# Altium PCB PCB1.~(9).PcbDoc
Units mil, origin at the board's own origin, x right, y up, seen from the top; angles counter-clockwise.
Board outline 1575 x 2005 mil, 2 copper layers (Top Layer, Bottom Layer); 15 components, 10 nets, 36 pads, 0 vias.
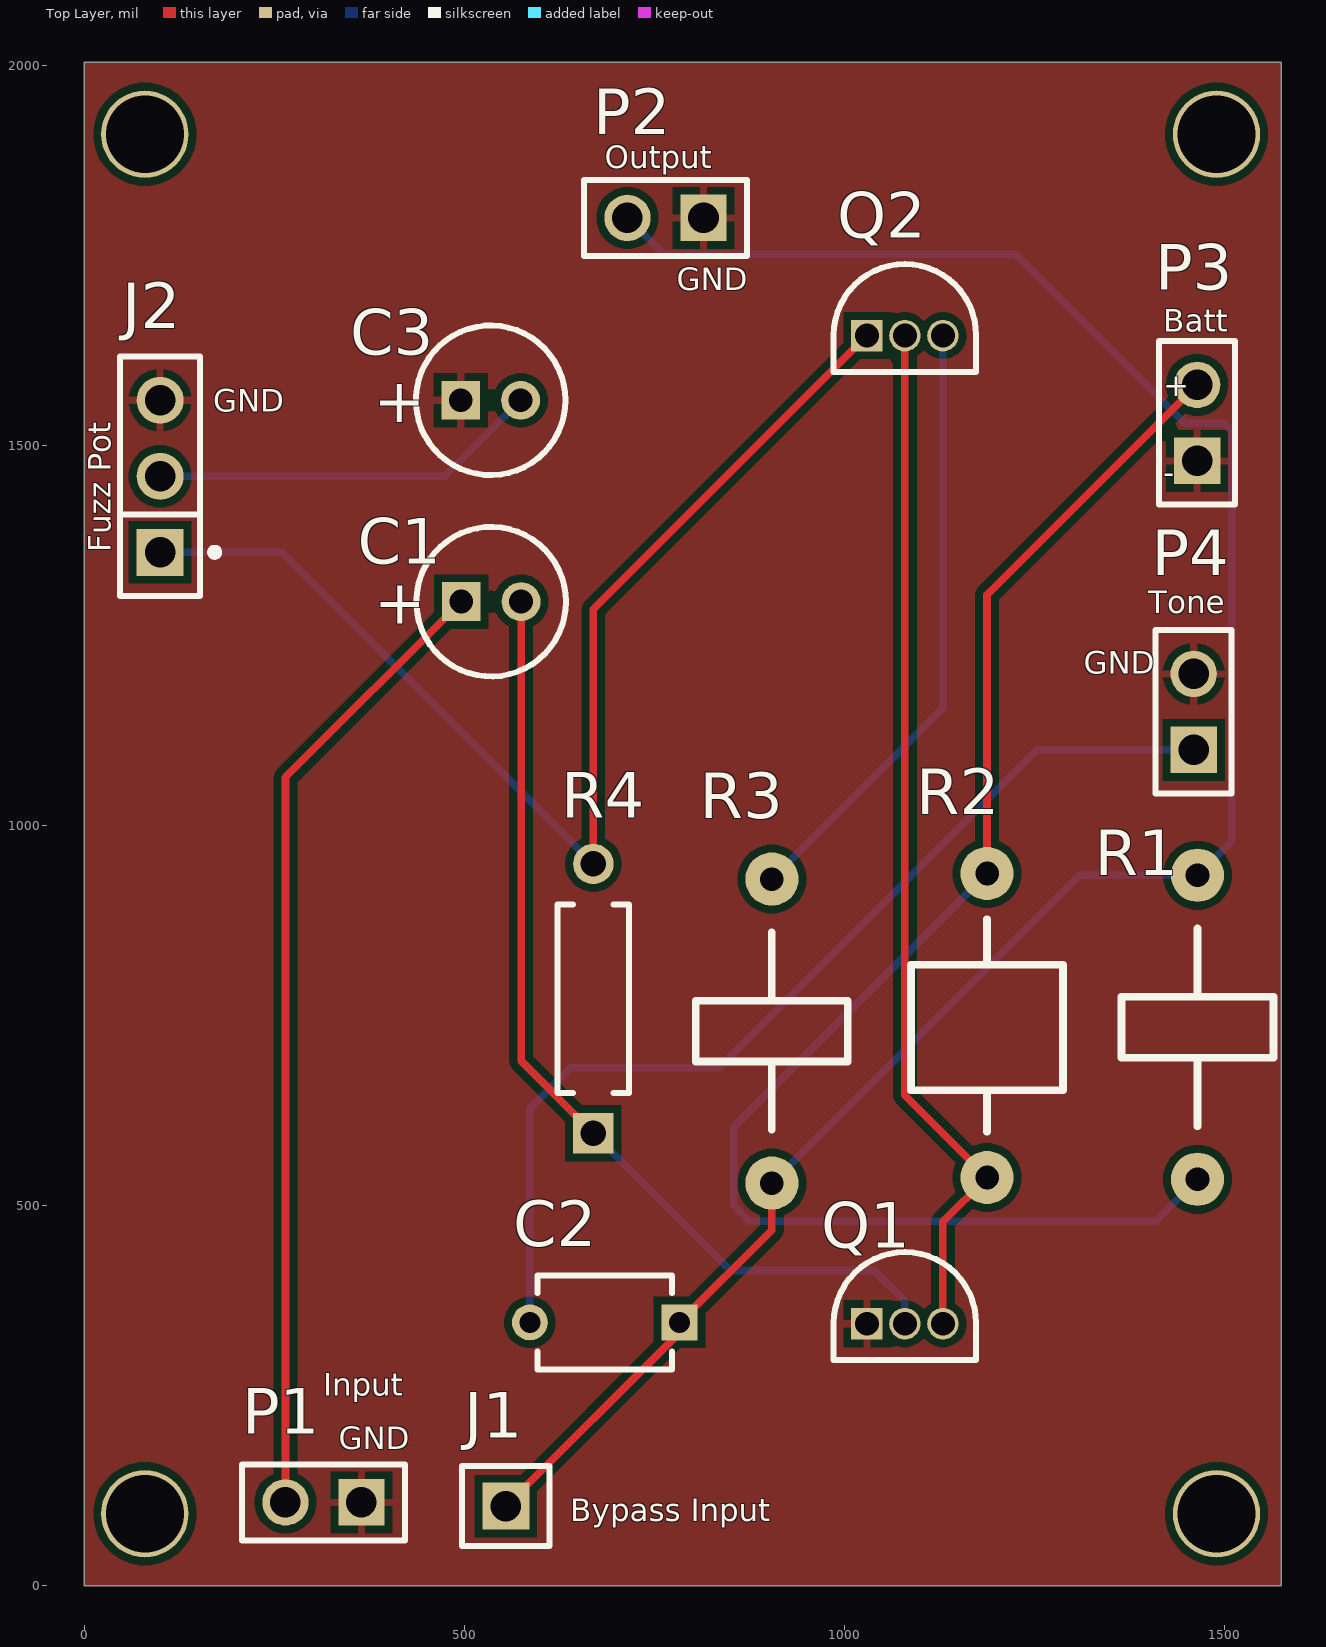
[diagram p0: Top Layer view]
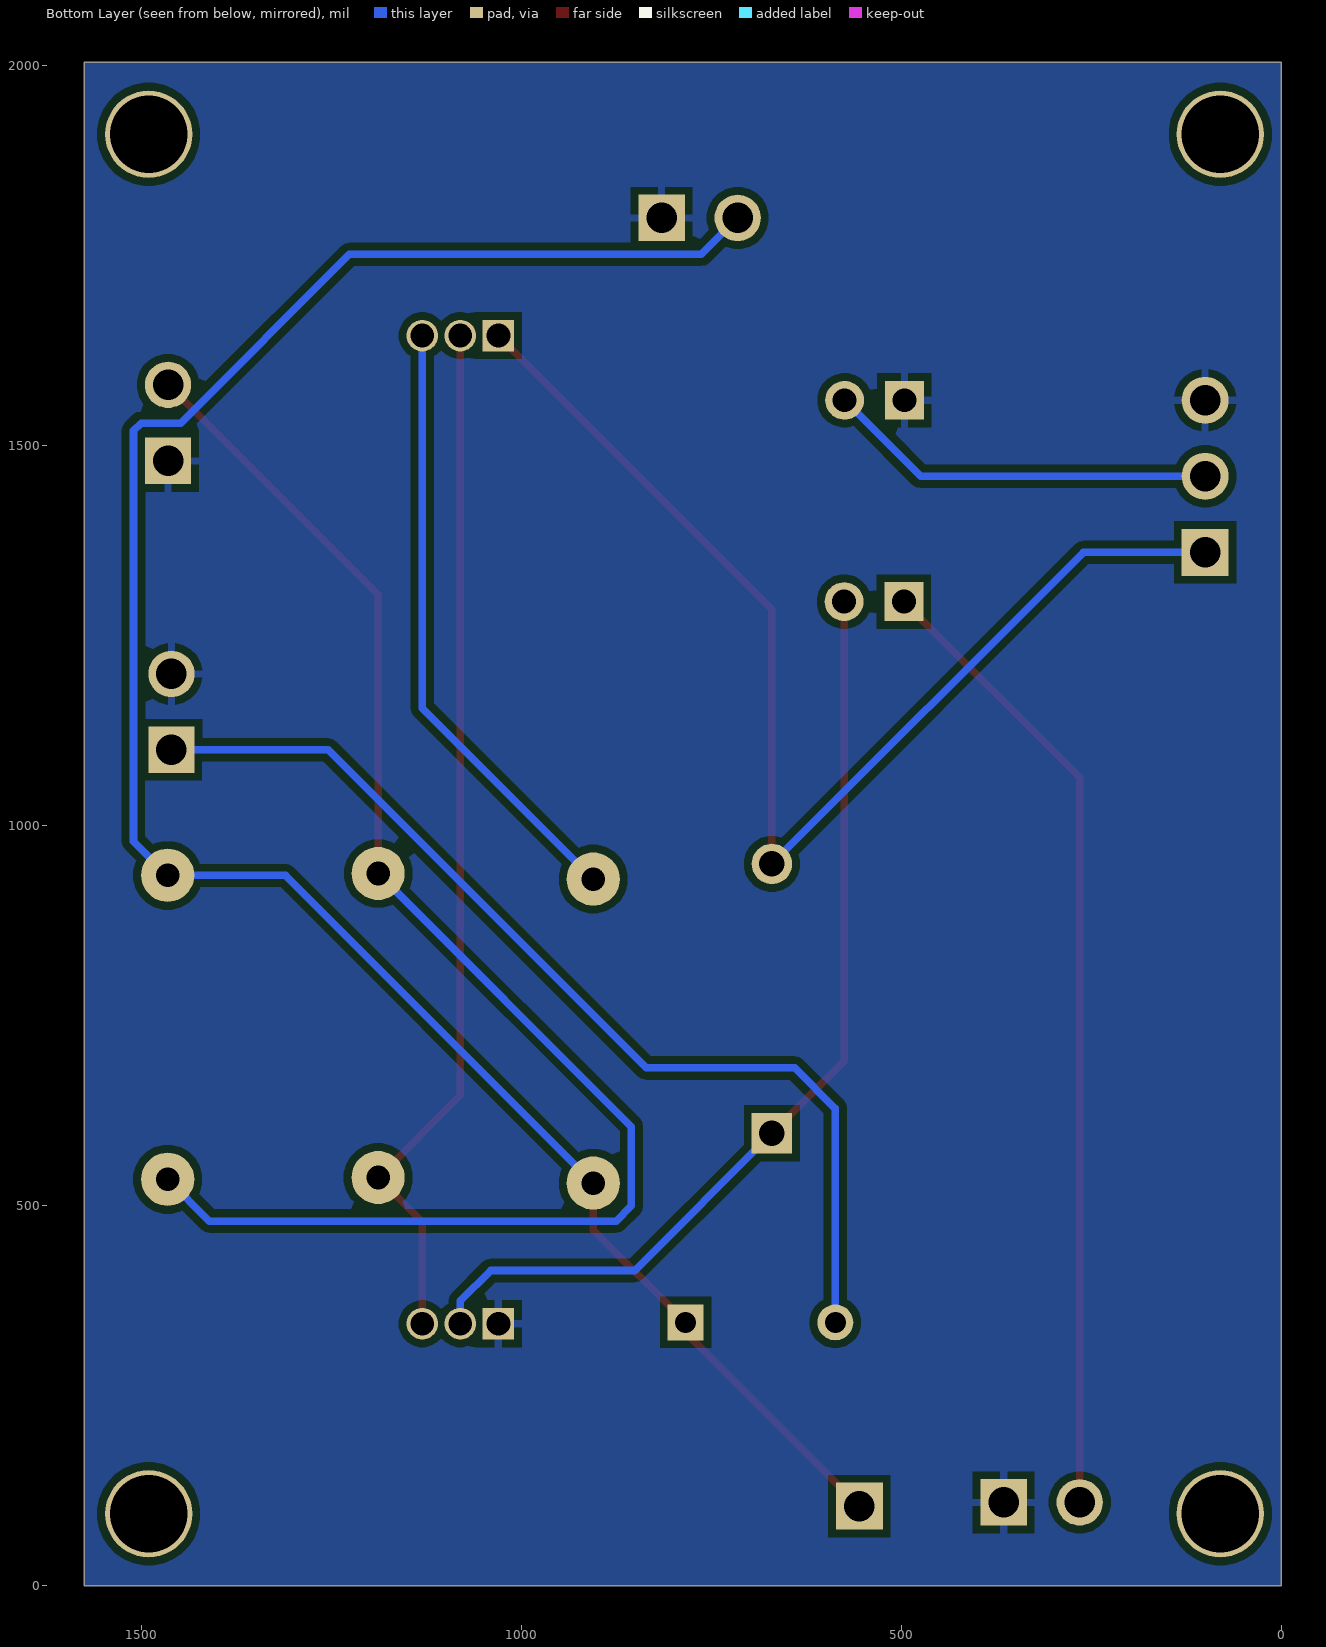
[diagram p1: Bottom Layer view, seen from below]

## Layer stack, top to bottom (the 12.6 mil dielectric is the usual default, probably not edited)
Top Solder: solder mask 0.4, Solder Resist, Dk 3.5
Top Layer: signal copper 1.4
Dielectric 1: dielectric 12.6, FR-4, Dk 4.8
Bottom Layer: signal copper 1.4
Bottom Solder: solder mask 0.4, Solder Resist, Dk 3.5

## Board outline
0,2005 1575,2005 1575,0 0,0
board region "Default Layer Stack Region": 0,1995.46 0,2005 1575,2005 1575,1995
board region "Default Layer Stack Region": 1575,1995 1575,0 0,0 0,1995.46

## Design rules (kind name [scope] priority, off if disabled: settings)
Clearance [All] p1: gap=10 ignorepadtopadclearanceinfootprint=TRUE
PolygonConnect [All] p1: connectstyle=Relief reliefconductorwidth=10 reliefentries=4 polygonreliefangle="90 Angle" airgapwidth=10
RoutingVias [All] p1: holewidth=28 width=50 viastyle="Through Hole" minholewidth=28 minwidth=50 maxholewidth=28 maxwidth=50
SolderMaskExpansion [All] p1: expansion=4 istentingtop=FALSE
SupplyNets "Schematic Supply Nets" [InNet('GND')] p1: voltage=0.000
Width [All] p1: maxlimit=15 minlimit=10 preferedwidth=15 minimp=50.000000 maximp=50.000000 favimp=50.000000
30 further rules are at their usual default settings.

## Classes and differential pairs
component class Sheetpcb: C1 C2 C3 J1 P1 P2 P3 P4 Q1 Q2 R1 R2 R3 R4

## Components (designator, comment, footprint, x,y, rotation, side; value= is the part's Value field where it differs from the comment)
C1 "ECA1HM2R2" CAPPR55-200-1100X500X1200 535.63,1295 r0 top value=2.2µF
C2 "RDER72H103K1K1H03B" FP-RDE1K1-MFG 685,346.71 r180 top
C3 "ECA1HM220" CAPPR55-200-1100X500X1200 535,1560 r0 top value=22µF
J1 "TSW-101-07-F-S" FP-TSW-101-07-F-S-MFG 555,105 r0 top
J2 "TSW-103-14-G-S" FP-TSW-103-14-G-S-MFG 100,1460 r90 top
P1 "TSW-102-26-G-S" SMTC-TSW-102-26-XX-S 365,110 r180 top
P2 "TSW-102-26-G-S" SMTC-TSW-102-26-XX-S 815,1800 r180 top
P3 "TSW-102-26-G-S" SMTC-TSW-102-26-XX-S 1464.49,1480.33 r90 top
P4 "TSW-102-26-G-S" SMTC-TSW-102-26-XX-S 1460,1100 r90 top
Q1 "2N3904BU" FAIR-TO-92 1030,345 r0 top
Q2 "2N3904BU" FAIR-TO-92 1030,1645 r0 top
R1 "470 Ohm Generic Resistor" "470 Ohm Resistor" 1465,535 r90 top value=470
R2 "33K Ohm Generic Through Hole Resistor" "Resistor 33K ohm" 1188.07,537.37 r90 top value=33k
R3 "820 Ohm Generic Resistor" "Resistor 820 Ohm Generic" 905,530 r90 top value=820
R4 "MFR-25FBF52-100K" RESA60-630X240 670,772.83 r90 top value=100k

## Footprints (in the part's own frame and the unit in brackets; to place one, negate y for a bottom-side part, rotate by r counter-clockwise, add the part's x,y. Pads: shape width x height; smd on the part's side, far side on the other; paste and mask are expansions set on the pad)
"470 Ohm Resistor" [mil]
  round 70 hole 31: 1(0,0) 2(400,0)
  silkscreen extent 70,-100 330,100
CAPPR55-200-1100X500X1200 [mm] "THD, 2-Leads, Dia 5mm, Pin Spacing 2mm"
  rect 1.3x1.3 hole 0.8: 1(-1,0)
  round 1.3 hole 0.8: 2(1,0)
  silkscreen extent -2.5,-2.5 2.5,2.5, body extent -2.5,-2.5 2.45,2.5, height 12
FAIR-TO-92 [mm] "TO, 3-Leads, Body Dia 4.79mm, Pitch 1.27mm"
  rect 1.05x1.05 hole 0.8 mask+0.05: 1(0,0)
  round 1.05 hole 0.8 mask+0.05: 2(1.27,0) 3(2.54,0)
  silkscreen extent -1.11,-1.21 3.65,2.4, body extent -1.11,-1.21 3.65,2.4, height 5.33
FP-RDE1K1-MFG [mm]
  rect 1.2x1.2 hole 0.7 paste-2539.97 mask+0: 1(-2.5,0)
  round 1.2 hole 0.7 paste-2539.97 mask+0: 2(2.5,0)
  silkscreen extent -2.25,-1.58 2.25,1.57, body extent -3.2,-1.68 3.2,1.68, height 0.25
FP-TSW-101-07-F-S-MFG [mm]
  rect 1.57x1.57 hole 1.02 paste-2539.97 mask+0: 1(0,0)
  silkscreen extent -1.46,-1.34 1.46,1.34, body extent -1.56,-1.44 1.56,1.44, height 0.25
FP-TSW-103-14-G-S-MFG [mm]
  rect 1.57x1.57 hole 1.02 paste-2539.97 mask+0: 1(-2.54,0)
  round 1.57 hole 1.02 paste-2539.97 mask+0: 2(0,0) 3(2.54,0)
  silkscreen extent -4,-1.95 4,1.34, body extent -4.1,-1.44 4.1,1.44, height 0.25
RESA60-630X240 [mm] "Axial Resistor, 2-Leads, Dia 2.4mm, Body Length 6.3mm"
  rect 1.35x1.35 hole 0.85: 1(-4.5,0)
  round 1.35 hole 0.85: 2(4.5,0)
  silkscreen extent -3.15,-1.2 3.15,1.2, body extent -4.77,-1.19 4.77,1.2, height 2.4
"Resistor 33K ohm" [mil]
  round 70 hole 31: 1(0,0) 2(400,0)
  silkscreen extent 60,-100 340,100
"Resistor 820 Ohm Generic" [mil]
  round 70 hole 31: 1(0,0) 2(400,0)
  silkscreen extent 70,-100 330,100
SMTC-TSW-102-26-XX-S [mm] ".025 SQ Post Terminal Strip Assembly, 1x2 Pins, Vertical, 2.54mm Pitch, Male"
  rect 1.55x1.55 hole 1.02: 1(0,0)
  round 1.55 hole 1.02: 2(2.54,0)
  silkscreen extent -1.46,-1.27 4,1.27, body extent -1.4,-1.27 3.81,1.27, height 8.38

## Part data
C1: library part CMP-001-00029-7, "Aluminum Electrolytic Capacitor, 2.2 uF, +/- 20%, 50 V, -40 to 85 degC, 2-Pin THD, RoHS, Bulk", Capacitor Type=Electrolytic, Case/Package=Radial, Manufacturer=Panasonic, Max Operating Temperature=85°C, Min Operating Temperature=-40°C, Package Description="2-Pin Radial Lead, Dia 5 mm, Height 12 mm", Package Quantity=200, Package Reference=CAPPR55-200-1100X500X1200, Ripple Current=20mA, Tolerance=20%, Voltage Rating=50V
C2: library part CMP-06035-024341-1, "Ceramic Capacitor 10nF ±10% 500V X7R Radial"
C3: library part CMP-001-00027-7, "Aluminum Electrolytic Capacitor, 22 uF, +/- 20%, 50 V, -40 to 85 degC, 2-Pin THD, RoHS, Bulk", Capacitor Type=Electrolytic, Case/Package=Radial, Manufacturer=Panasonic, Max Operating Temperature=85°C, Min Operating Temperature=-40°C, Package Description="2-Pin Radial Lead, Dia 5 mm, Height 12 mm", Package Quantity=200, Package Reference=CAPPR55-200-1100X500X1200, Ripple Current=100mA, Tolerance=20%, Voltage Rating=50V
J1: library part CMP-02766-001403-1, "CONN HEADER VERT 1POS", Flammability Rating="UL94 V-0", Insulation Color=Black, Max Operating Temperature=125°C, Min Operating Temperature=-55°C
J2: library part CMP-02766-001743-1, "CONN HEADER VERT 3POS 2.54MM", Color=Black, Flammability Rating="UL94 V-0", Max Current Rating=7.6A, Max Operating Temperature=125°C, Max Voltage Rating (AC)=550V, Min Operating Temperature=-55°C, Package Quantity=1
P1 P2 P3 P4: library part CMP-1024-00327-1, "0.025\" SQ Post Header, Through-hole, Vertical, -55 to 125 degC, 2.54 mm Pitch, 2-Pin, Male, RoHS", Manufacturer=Samtec, Temperature Range="-55 to 125 degC"
Q1 Q2: library part CMP-2000-04944-1, "NPN General-Purpose Amplifier, 40 V VCEO, 0.2 A, -55 to 150 degC, 2-Pin TO-92, RoHS, Bulk", Manufacturer=FairchildSemiconductor, Maximum Collector Base Voltage=60V, Maximum Collector Emitter Saturation Voltage=0.2@1mA@10mA, Maximum Collector Emitter Voltage=40V, Maximum DC Collector Current=0.2A, Maximum Operating Frequency=300(Min)MHz, Maximum Power Dissipation=625mW, Minimum DC Current Gain=40@0.1mA@1V, Operating Temperature=-55to150degC, Package=3TO-92, Package Description="3-Pin Transistor Outline Package, Body Dia 4.79 mm, Pitch 1.27 mm", Package Reference=TO-92
R1: library part CMP-009-00178-1, Power=250mW
R2: library part CMP-009-00177-1, Power=250mW
R3: library part CMP-009-00179-1, Power=250mW
R4: library part CMP-009-00045-4, "Axial Resistor, 100 KOhm, +/- 1%, 0.25 W, -55 to 155 degC, 2-Pin THD, RoHS, Bulk", Case/Package=Axial, Manufacturer=Yageo, Max Operating Temperature=155°C, Min Operating Temperature=-55°C, Package Description="2-Pin Axial Lead, Dia 2.4 mm, Body Length 6.3 mm", Package Quantity=200, Package Reference=MFR-25, Power=250mW, Tolerance=1%, Voltage Rating=250V

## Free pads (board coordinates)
  round 115 hole 102.36 unplated: 1(80,1910) 2(1490,1910) 3(1490,95)
  round 115 hole 102.36: 4(80,95)

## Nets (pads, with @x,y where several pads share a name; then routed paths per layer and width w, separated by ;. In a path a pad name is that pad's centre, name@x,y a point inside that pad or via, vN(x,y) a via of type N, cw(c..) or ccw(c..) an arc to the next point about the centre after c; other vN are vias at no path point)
GND: C3.1 J2.3 P1.1 P2.1 P3.1 P4.2 Q1.1
NetC1_1: C1.1 P1.2 | length 1280.8
  Top Layer w10: P1.2 265,1063.74 C1.1
NetC1_2: C1.2 Q1.2 R4.1 | length 1270.1
  Top Layer w10: C1.2 575,690.67 R4.1
  Bottom Layer w10: R4.1 850.67,415 1040,415 1080,375 Q1.2
NetC2_1: C2.1 J1.1 P2.2 R1.2 R3.1 | length 2812.4
  Top Layer w10: J1.1 783.43,333.43 C2.1 905,468.29 R3.1
  Bottom Layer w10: P2.2 763,1752 1226,1752 1448,1530 1500,1530 1510,1520 1510,980 R1.2 1310,935 R3.1
NetC2_2: C2.2 P4.1 | length 1350.3
  Bottom Layer w10: C2.2 586.57,628.15 640,681.57 835.57,681.57 1254,1100 P4.1
NetC3_2: C3.2 J2.2 | length 515.8
  Bottom Layer w10: J2.2 474.37,1460 C3.2
NetJ2_1: J2.1 Q2.1 R4.2 | length 1583.9
  Top Layer w10: R4.2 670,1285 Q2.1
  Bottom Layer w10: J2.1 260,1360 R4.2
NetP3_2: P3.2 R1.1 R2.2 | length 1973.9
  Top Layer w10: R2.2 1188.07,1303.91 P3.2
  Bottom Layer w10: R2.2 855,604.3 855,500 875,480 1410,480 R1.1
NetQ1_3: Q1.3 Q2.2 R2.1 | length 1368.8
  Top Layer w10: Q2.2 1080,645.44 R2.1 1130,479.3 Q1.3
NetQ2_3: Q2.3 R3.2 | length 808.2
  Bottom Layer w10: R3.2 1130,1155 Q2.3

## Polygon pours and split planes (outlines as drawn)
GND on Bottom Layer "GND_L02_P000" (solid, pour order 0): 0,0 1575,0 1575,2005 0,2005
GND on Top Layer "GND_L01_P001" (solid, pour order 1): 0,0 1575,0 1575,2005 0,2005

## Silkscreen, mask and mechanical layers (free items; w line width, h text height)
Top Overlay:
  text "Output" at 685,1865 h30
  text "GND" at 780,1705 h30
  text "Batt" at 1420,1650 h30
  text "+" at 1420,1565 h30
  text "GND" at 170,1545 h30
  text "-" at 1420,1450 h30
  text "Fuzz Pot" at 35,1360 h30 r90
  text "Tone" at 1400,1280 h30
  text "GND" at 1315,1200 h30
  text "Input" at 315,250 h30
  text "GND" at 335,180 h30
  text "Bypass Input" at 640,85 h30

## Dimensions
80,1910 to 80,95 on Top Overlay
1490,95 to 1490,1910 on Top Overlay
80,95 to 1490,95 on Top Overlay
80,1910 to 1490,1910 on Top Overlay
